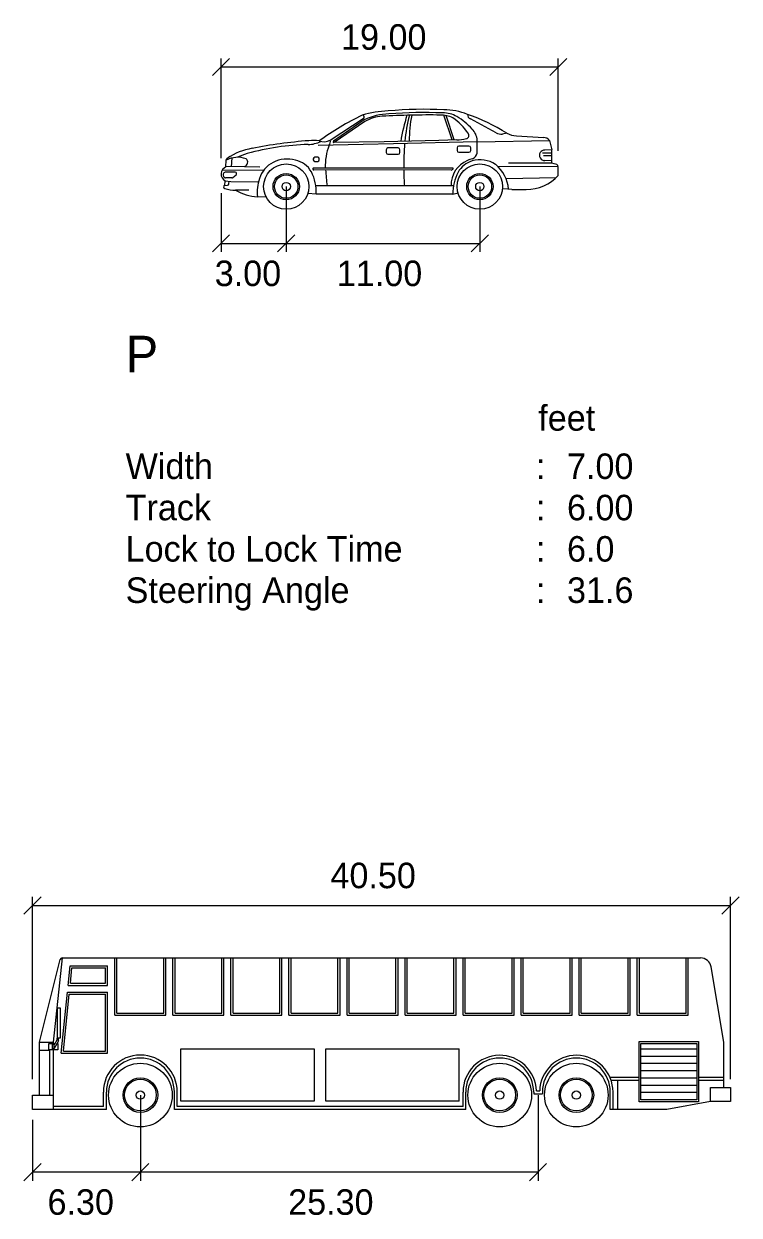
# Model space of a CAD drawing. Extents: x 2297881 to 2300600, y 559917 to 564426.
# Drawn here: x 2299070.1 to 2299106.9, y 562689.6 to 562750.9 of the extents above; entities that cross this region are included whole.
import ezdxf

# ---------------------------------------------------------------- set-up
doc = ezdxf.new("R2010")
doc.units = 0
doc.layers.add('DR_X_Elev_Flow', color=7, linetype='Continuous')

msp = doc.modelspace()

# ---------------------------------------------------------------- linework, layer by layer
at = {"layer": 'DR_X_Elev_Flow'}
for p, q in [((2299080.691, 562749.141), (2299079.805, 562748.255)), ((2299080.248, 562744.013), (2299080.248, 562749.141)), ((2299080.248, 562748.698), (2299097.593, 562748.698)), ((2299098.036, 562749.141), (2299097.15, 562748.255)), ((2299097.593, 562744.38), (2299097.593, 562749.141)), ((2299092.139, 562744.947), (2299091.71, 562746.216)), ((2299085.861, 562744.935), (2299087.611, 562746.084)), ((2299087.603, 562745.985), (2299086.034, 562744.873)), ((2299087.651, 562745.896), (2299086.071, 562744.807)), ((2299092.243, 562744.951), (2299091.824, 562746.199)), ((2299094.394, 562745.31), (2299093.077, 562746.026)), ((2299094.94, 562745.29), (2299094.721, 562745.249)), ((2299095.438, 562745.154), (2299096.83, 562745.065)), ((2299087.552, 562744.71), (2299085.242, 562744.655)), ((2299088.643, 562744.847), (2299086.055, 562744.806)), ((2299089.124, 562744.751), (2299087.552, 562744.71)), ((2299091.451, 562744.921), (2299088.643, 562744.847)), ((2299088.742, 562744.438), (2299088.742, 562744.302)), ((2299089.353, 562744.53), (2299088.834, 562744.53)), ((2299093.423, 562744.843), (2299089.124, 562744.751)), ((2299089.445, 562744.302), (2299089.445, 562744.438)), ((2299092.372, 562744.955), (2299091.451, 562744.921)), ((2299092.386, 562744.54), (2299092.386, 562744.404)), ((2299092.997, 562744.632), (2299092.478, 562744.632)), ((2299093.089, 562744.404), (2299093.089, 562744.54)), ((2299093.416, 562744.703), (2299093.423, 562744.921)), ((2299093.416, 562744.264), (2299093.416, 562744.703)), ((2299093.423, 562744.843), (2299097.144, 562744.924)), ((2299097.259, 562744.438), (2299096.899, 562744.425)), ((2299097.144, 562744.924), (2299097.259, 562744.438)), ((2299097.262, 562743.864), (2299097.259, 562744.438)), ((2299080.499, 562743.556), (2299080.513, 562743.905)), ((2299080.513, 562743.905), (2299080.577, 562744.006)), ((2299080.792, 562743.562), (2299080.817, 562744.017)), ((2299081.599, 562744.248), (2299081.091, 562744.05)), ((2299084.993, 562743.98), (2299084.993, 562743.916)), ((2299085.226, 562744.054), (2299085.067, 562744.054)), ((2299085.067, 562743.843), (2299085.226, 562743.843)), ((2299085.3, 562743.916), (2299085.3, 562743.98)), ((2299088.834, 562744.21), (2299089.353, 562744.21)), ((2299092.478, 562744.312), (2299092.997, 562744.312)), ((2299097.259, 562743.745), (2299095.032, 562743.755)), ((2299097.26, 562744.27), (2299096.786, 562744.267)), ((2299097.261, 562744.128), (2299096.826, 562744.132)), ((2299097.262, 562743.864), (2299096.895, 562743.881)), ((2299097.259, 562743.745), (2299097.262, 562743.864)), ((2299082.435, 562743.376), (2299080.306, 562743.396)), ((2299080.98, 562743.279), (2299080.454, 562743.279)), ((2299081.449, 562743.577), (2299080.499, 562743.556)), ((2299080.858, 562743.01), (2299081.027, 562743.148)), ((2299081.449, 562743.577), (2299082.249, 562743.556)), ((2299092.192, 562743.493), (2299084.983, 562743.496)), ((2299092.076, 562743.391), (2299085.018, 562743.4)), ((2299097.593, 562743.56), (2299094.491, 562743.574)), ((2299097.383, 562743.712), (2299097.259, 562743.745)), ((2299097.593, 562743.12), (2299097.593, 562743.56)), ((2299080.444, 562742.604), (2299080.462, 562742.846)), ((2299080.444, 562742.604), (2299080.588, 562742.618)), ((2299080.462, 562742.846), (2299080.752, 562742.803)), ((2299080.811, 562742.993), (2299080.469, 562742.993)), ((2299080.654, 562742.689), (2299080.658, 562742.817)), ((2299080.752, 562742.803), (2299082.138, 562742.796)), ((2299083.6, 562742.545), (2299083.6, 562739.183)), ((2299089.438, 562742.58), (2299085.123, 562742.589)), ((2299092.202, 562742.58), (2299089.438, 562742.58)), ((2299093.557, 562742.545), (2299093.557, 562739.183)), ((2299097.48, 562743.003), (2299094.91, 562742.938)), ((2299080.248, 562742.211), (2299080.248, 562739.183)), ((2299081.68, 562742.361), (2299080.987, 562742.354)), ((2299082.125, 562742.013), (2299082.548, 562742.043)), ((2299085.138, 562742.152), (2299084.709, 562742.186)), ((2299092.177, 562742.156), (2299085.138, 562742.152)), ((2299092.177, 562742.156), (2299092.437, 562742.229)), ((2299094.992, 562742.42), (2299094.718, 562742.423)), ((2299095.199, 562742.399), (2299094.992, 562742.42)), ((2299095.199, 562742.399), (2299095.939, 562742.399)), ((2299080.691, 562740.069), (2299079.805, 562739.183)), ((2299080.248, 562739.626), (2299093.557, 562739.626)), ((2299084.043, 562740.069), (2299083.157, 562739.183)), ((2299094, 562740.069), (2299093.114, 562739.183)), ((2299070.991, 562706.019), (2299070.105, 562705.133)), ((2299070.548, 562696.635), (2299070.548, 562706.019)), ((2299106.895, 562706.019), (2299106.009, 562705.133)), ((2299106.452, 562696.635), (2299106.452, 562706.019)), ((2299070.548, 562705.576), (2299106.452, 562705.576)), ((2299070.917, 562698.544), (2299071.967, 562702.792)), ((2299072.072, 562702.875), (2299071.615, 562698.538)), ((2299072.073, 562702.875), (2299104.911, 562702.875)), ((2299074.787, 562699.93), (2299074.787, 562702.875)), ((2299074.896, 562700.04), (2299074.896, 562702.875)), ((2299077.303, 562700.04), (2299077.303, 562702.875)), ((2299077.412, 562699.93), (2299077.412, 562702.875)), ((2299077.772, 562699.93), (2299077.772, 562702.875)), ((2299077.881, 562700.04), (2299077.881, 562702.875)), ((2299080.288, 562700.04), (2299080.288, 562702.875)), ((2299080.397, 562699.93), (2299080.397, 562702.875)), ((2299080.757, 562699.93), (2299080.757, 562702.875)), ((2299080.866, 562700.04), (2299080.866, 562702.875)), ((2299083.273, 562700.04), (2299083.273, 562702.875)), ((2299083.382, 562699.93), (2299083.382, 562702.875)), ((2299083.742, 562699.93), (2299083.742, 562702.875)), ((2299083.851, 562700.04), (2299083.851, 562702.875)), ((2299086.258, 562700.04), (2299086.258, 562702.875)), ((2299086.367, 562699.93), (2299086.367, 562702.875)), ((2299086.727, 562699.93), (2299086.727, 562702.875)), ((2299086.837, 562700.04), (2299086.837, 562702.875)), ((2299089.243, 562700.04), (2299089.243, 562702.875)), ((2299089.352, 562699.93), (2299089.352, 562702.875)), ((2299089.712, 562699.93), (2299089.712, 562702.875)), ((2299089.822, 562700.04), (2299089.822, 562702.875)), ((2299092.228, 562700.04), (2299092.228, 562702.875)), ((2299092.337, 562699.93), (2299092.337, 562702.875)), ((2299092.697, 562699.93), (2299092.697, 562702.875)), ((2299092.807, 562700.04), (2299092.807, 562702.875)), ((2299095.213, 562700.04), (2299095.213, 562702.875)), ((2299095.322, 562699.93), (2299095.322, 562702.875)), ((2299095.682, 562699.93), (2299095.682, 562702.875)), ((2299095.792, 562700.04), (2299095.792, 562702.875)), ((2299098.198, 562700.04), (2299098.198, 562702.875)), ((2299098.307, 562699.93), (2299098.307, 562702.875)), ((2299098.667, 562699.93), (2299098.667, 562702.875)), ((2299098.777, 562700.04), (2299098.777, 562702.875)), ((2299101.183, 562700.04), (2299101.183, 562702.875)), ((2299101.293, 562699.93), (2299101.293, 562702.875)), ((2299101.653, 562699.93), (2299101.653, 562702.875)), ((2299101.762, 562700.04), (2299101.762, 562702.875)), ((2299104.168, 562700.04), (2299104.168, 562702.875)), ((2299104.278, 562699.93), (2299104.278, 562702.875)), ((2299072.381, 562701.463), (2299072.483, 562702.477)), ((2299072.483, 562702.477), (2299074.407, 562702.477)), ((2299072.502, 562701.573), (2299072.582, 562702.367)), ((2299072.582, 562702.367), (2299074.298, 562702.367)), ((2299074.298, 562701.573), (2299074.298, 562702.367)), ((2299074.407, 562701.463), (2299074.407, 562702.477)), ((2299106.113, 562698.544), (2299105.45, 562702.42)), ((2299072.502, 562701.573), (2299074.298, 562701.573)), ((2299072.03, 562697.971), (2299072.346, 562701.118)), ((2299072.15, 562698.08), (2299072.445, 562701.008)), ((2299072.346, 562701.118), (2299074.407, 562701.118)), ((2299072.381, 562701.463), (2299074.407, 562701.463)), ((2299072.445, 562701.008), (2299074.298, 562701.008)), ((2299074.298, 562698.08), (2299074.298, 562701.008)), ((2299074.407, 562697.971), (2299074.407, 562701.118)), ((2299071.819, 562700.304), (2299071.819, 562698.741)), ((2299071.819, 562700.304), (2299071.977, 562700.304)), ((2299071.977, 562700.304), (2299071.977, 562698.741)), ((2299074.787, 562699.93), (2299077.412, 562699.93)), ((2299074.896, 562700.04), (2299077.303, 562700.04)), ((2299077.772, 562699.93), (2299080.397, 562699.93)), ((2299077.881, 562700.04), (2299080.288, 562700.04)), ((2299080.757, 562699.93), (2299083.382, 562699.93)), ((2299080.866, 562700.04), (2299083.273, 562700.04)), ((2299083.742, 562699.93), (2299086.367, 562699.93)), ((2299083.851, 562700.04), (2299086.258, 562700.04)), ((2299086.727, 562699.93), (2299089.352, 562699.93)), ((2299086.837, 562700.04), (2299089.243, 562700.04)), ((2299089.712, 562699.93), (2299092.337, 562699.93)), ((2299089.822, 562700.04), (2299092.228, 562700.04)), ((2299092.697, 562699.93), (2299095.322, 562699.93)), ((2299092.807, 562700.04), (2299095.213, 562700.04)), ((2299095.682, 562699.93), (2299098.307, 562699.93)), ((2299095.792, 562700.04), (2299098.198, 562700.04)), ((2299098.667, 562699.93), (2299101.293, 562699.93)), ((2299098.777, 562700.04), (2299101.183, 562700.04)), ((2299101.653, 562699.93), (2299104.278, 562699.93)), ((2299101.762, 562700.04), (2299104.168, 562700.04)), ((2299070.917, 562695.815), (2299070.917, 562698.544)), ((2299070.917, 562698.544), (2299071.616, 562698.544)), ((2299071.395, 562698.48), (2299071.709, 562698.48)), ((2299071.395, 562698.156), (2299071.395, 562698.48)), ((2299071.583, 562698.205), (2299071.583, 562698.432)), ((2299071.671, 562698.432), (2299071.583, 562698.432)), ((2299071.615, 562698.538), (2299071.615, 562698.48)), ((2299071.819, 562698.68), (2299071.671, 562698.41)), ((2299071.889, 562698.619), (2299071.671, 562698.222)), ((2299071.671, 562698.205), (2299071.671, 562698.432)), ((2299071.813, 562698.48), (2299071.859, 562698.48)), ((2299071.977, 562698.741), (2299071.819, 562698.741)), ((2299071.819, 562698.68), (2299071.819, 562698.741)), ((2299071.859, 562698.48), (2299071.859, 562698.156)), ((2299071.889, 562698.619), (2299071.889, 562698.741)), ((2299101.748, 562695.483), (2299101.748, 562698.575)), ((2299101.748, 562698.575), (2299104.803, 562698.575)), ((2299101.841, 562695.576), (2299101.841, 562698.482)), ((2299101.841, 562698.482), (2299104.71, 562698.482)), ((2299104.71, 562698.482), (2299104.71, 562695.576)), ((2299104.803, 562698.575), (2299104.803, 562695.483)), ((2299106.113, 562696.218), (2299106.113, 562698.544)), ((2299071.441, 562698.117), (2299070.917, 562698.117)), ((2299071.859, 562698.156), (2299071.395, 562698.156)), ((2299071.441, 562695.815), (2299071.441, 562698.117)), ((2299071.671, 562698.205), (2299071.583, 562698.205)), ((2299071.615, 562698.156), (2299071.615, 562695.088)), ((2299072.03, 562697.971), (2299074.407, 562697.971)), ((2299072.15, 562698.08), (2299074.298, 562698.08)), ((2299078.181, 562698.207), (2299085.04, 562698.207)), ((2299078.181, 562695.503), (2299078.181, 562698.207)), ((2299085.04, 562698.207), (2299085.04, 562695.503)), ((2299085.639, 562695.503), (2299085.639, 562698.207)), ((2299085.639, 562698.207), (2299092.498, 562698.207)), ((2299092.498, 562695.503), (2299092.498, 562698.207)), ((2299104.71, 562698.184), (2299101.841, 562698.184)), ((2299104.71, 562697.811), (2299101.841, 562697.811)), ((2299104.71, 562697.439), (2299101.841, 562697.439)), ((2299101.748, 562696.721), (2299100.256, 562696.721)), ((2299104.71, 562697.066), (2299101.841, 562697.066)), ((2299104.71, 562696.694), (2299101.841, 562696.694)), ((2299106.113, 562696.721), (2299104.803, 562696.721)), ((2299074.199, 562695.243), (2299074.199, 562695.98)), ((2299074.353, 562695.088), (2299074.353, 562695.98)), ((2299077.846, 562695.088), (2299077.846, 562695.98)), ((2299077.999, 562695.241), (2299077.999, 562695.98)), ((2299092.693, 562695.241), (2299092.693, 562695.98)), ((2299092.832, 562695.088), (2299092.832, 562695.98)), ((2299096.326, 562695.98), (2299096.326, 562695.882)), ((2299096.465, 562696.035), (2299096.636, 562696.035)), ((2299096.774, 562695.98), (2299096.774, 562695.882)), ((2299100.268, 562695.088), (2299100.268, 562695.98)), ((2299101.748, 562696.571), (2299100.313, 562696.571)), ((2299100.408, 562695.088), (2299100.408, 562695.98)), ((2299100.632, 562696.571), (2299100.632, 562695.088)), ((2299104.71, 562696.321), (2299101.841, 562696.321)), ((2299106.113, 562696.571), (2299104.803, 562696.571)), ((2299105.415, 562695.489), (2299105.415, 562696.218)), ((2299105.415, 562696.218), (2299106.452, 562696.218)), ((2299106.452, 562696.218), (2299106.452, 562695.489)), ((2299070.548, 562695.088), (2299070.548, 562695.815)), ((2299070.548, 562695.815), (2299071.615, 562695.815)), ((2299076.099, 562695.822), (2299076.099, 562691.42)), ((2299085.04, 562695.503), (2299078.181, 562695.503)), ((2299092.498, 562695.503), (2299085.639, 562695.503)), ((2299096.326, 562695.882), (2299096.774, 562695.882)), ((2299096.55, 562695.822), (2299096.55, 562691.42)), ((2299104.803, 562695.483), (2299101.748, 562695.483)), ((2299104.71, 562695.948), (2299101.841, 562695.948)), ((2299104.71, 562695.576), (2299101.841, 562695.576)), ((2299105.415, 562695.489), (2299103.183, 562695.088)), ((2299106.452, 562695.489), (2299105.415, 562695.489)), ((2299074.353, 562695.088), (2299070.548, 562695.088)), ((2299074.199, 562695.243), (2299071.615, 562695.243)), ((2299092.832, 562695.088), (2299077.846, 562695.088)), ((2299092.693, 562695.241), (2299077.999, 562695.241)), ((2299103.183, 562695.088), (2299100.268, 562695.088)), ((2299070.548, 562694.541), (2299070.548, 562691.42)), ((2299070.991, 562692.306), (2299070.105, 562691.42)), ((2299076.542, 562692.306), (2299075.656, 562691.42)), ((2299096.993, 562692.306), (2299096.107, 562691.42)), ((2299096.55, 562691.863), (2299070.548, 562691.863))]:
    msp.add_line(p, q, dxfattribs=at)
for centre, radius in [((2299083.6, 562742.545), 1.166), ((2299083.6, 562742.545), 0.677), ((2299083.6, 562742.545), 0.603), ((2299093.559, 562742.545), 1.166), ((2299093.559, 562742.545), 0.677), ((2299093.559, 562742.545), 0.603), ((2299083.598, 562742.545), 0.214), ((2299093.557, 562742.545), 0.214), ((2299076.099, 562695.822), 1.636), ((2299094.579, 562695.822), 1.636), ((2299098.521, 562695.822), 1.636), ((2299076.099, 562695.822), 0.891), ((2299076.099, 562695.822), 0.817), ((2299094.579, 562695.822), 0.891), ((2299094.579, 562695.822), 0.817), ((2299098.521, 562695.822), 0.891), ((2299098.521, 562695.822), 0.817), ((2299076.099, 562695.822), 0.214), ((2299094.579, 562695.822), 0.214), ((2299098.521, 562695.822), 0.214)]:
    msp.add_circle(centre, radius, dxfattribs=at)
for centre, radius, start, end in [((2299094.08, 562732.739), 14.995, 115.99712, 125.85948), ((2299089.005, 562741.248), 5.189, 91.77281, 106.76702), ((2299087.52, 562746.12), 0.098, 338.75119, 97.13803), ((2299089.008, 562742.873), 3.414, 92.05595, 114.28451), ((2299090.943, 562701.183), 45.045, 89.25909, 93.07428), ((2299090.734, 562725.354), 21.165, 87.35134, 95.12359), ((2299090.664, 562723.298), 23.056, 87.55301, 94.42581), ((2299099.097, 562743.294), 9.735, 162.55273, 170.6899), ((2299097.845, 562744.121), 8.179, 165.15925, 174.7143), ((2299096.14, 562744.957), 6.214, 168.28823, 180.7049), ((2299091.565, 562744.89), 1.334, 63.15401, 91.67876), ((2299091.665, 562744.857), 1.476, 61.06729, 90.63003), ((2299091.693, 562743.222), 3.275, 67.99072, 89.6559), ((2299093.181, 562746.266), 0.261, 181.61853, 246.57824), ((2299089.892, 562737.35), 9.408, 57.55295, 71.22582), ((2299088.676, 562744.096), 2.072, 94.12051, 119.6618), ((2299090.402, 562743.544), 3.091, 34.39064, 55.15895), ((2299090.545, 562743.155), 3.51, 41.92691, 58.50685), ((2299092.454, 562746.453), 1.5, 266.85027, 285.8201), ((2299092.823, 562745.176), 0.171, 283.52227, 41.26655), ((2299092.547, 562744.87), 0.877, 3.34282, 45.98534), ((2299094.67, 562745.881), 0.634, 244.14508, 274.63214), ((2299095.475, 562746.267), 1.114, 241.28844, 268.0918), ((2299096.837, 562744.661), 0.404, 40.57088, 90.99801), ((2299082.432, 562741.21), 3.355, 100.12542, 123.55743), ((2299085.109, 562731.36), 13.358, 91.63395, 105.23518), ((2299086.897, 562717.997), 26.993, 94.54819, 100.79455), ((2299084.721, 562746.142), 1.43, 270.28832, 297.12219), ((2299084.989, 562743.356), 1.567, 78.67608, 98.51403), ((2299085.53, 562745.552), 0.7, 250.49814, 298.18144), ((2299088.397, 562743.624), 2.79, 158.00531, 182.63231), ((2299085.566, 562744.853), 0.306, 323.15387, 15.54768), ((2299086.055, 562744.843), 0.0368, 125.3064, 270.88891), ((2299088.834, 562744.438), 0.0921, 90, 180), ((2299089.353, 562744.438), 0.0921, 0, 90), ((2299103.752, 562743.595), 14.111, 175.25332, 180.41419), ((2299092.478, 562744.54), 0.0921, 90, 180), ((2299092.478, 562744.404), 0.0921, 180, 270), ((2299092.997, 562744.54), 0.0921, 0, 90), ((2299092.997, 562744.404), 0.0921, 270, 0), ((2299096.896, 562744.153), 0.272, 89.43028, 269.87467), ((2299081.106, 562742.763), 1.288, 70.57617, 117.43529), ((2299081.392, 562743.799), 0.229, 284.46814, 51.32362), ((2299083.544, 562742.556), 1.38, 116.40845, 163.0738), ((2299083.647, 562742.335), 1.623, 74.93457, 116.18682), ((2299083.84, 562742.725), 1.2, 28.74798, 78.99952), ((2299085.067, 562743.98), 0.0736, 90, 180), ((2299085.067, 562743.916), 0.0736, 180, 270), ((2299085.226, 562743.98), 0.0736, 0, 90), ((2299085.226, 562743.916), 0.0736, 270, 360), ((2299088.834, 562744.302), 0.0921, 180, 270), ((2299089.353, 562744.302), 0.0921, 270, 0), ((2299093.434, 562742.626), 1.357, 112.09642, 181.96798), ((2299093.548, 562742.637), 1.288, 107.40375, 149.71305), ((2299093.337, 562743.12), 0.869, 100.40941, 118.442), ((2299093.562, 562742.398), 1.521, 58.12537, 105.22231), ((2299093.035, 562744.333), 0.387, 292.0027, 349.73442), ((2299080.637, 562743.193), 0.388, 110.80508, 243.2128), ((2299080.532, 562743.144), 0.173, 142.05963, 230.7171), ((2299080.454, 562743.205), 0.0736, 90, 142.05963), ((2299080.98, 562743.205), 0.0736, 309.39036, 90), ((2299082.996, 562742.294), 2.147, 356.20605, 28.00521), ((2299085.023, 562743.456), 0.0565, 134.52898, 265.08732), ((2299112.364, 562745.398), 26.813, 184.27566, 186.01704), ((2299096.256, 562743.207), 6.604, 178.40363, 185.45034), ((2299092.075, 562743.509), 0.118, 270.588, 352.21402), ((2299094.435, 562742.235), 2.26, 152.25545, 181.99873), ((2299093.11, 562742.209), 1.941, 6.08396, 49.72235), ((2299097.399, 562743.513), 0.2, 13.74091, 94.60676), ((2299080.455, 562742.529), 0.0757, 98.08536, 261.91464), ((2299080.469, 562743.067), 0.0736, 230.7171, 270), ((2299080.58, 562742.692), 0.0736, 275.90147, 358.12063), ((2299080.811, 562743.067), 0.0736, 270, 309.39036), ((2299084.159, 562742.277), 2.051, 160.61524, 187.39409), ((2299095.975, 562744.575), 2.176, 269.05415, 318.03413), ((2299081.004, 562743.969), 1.615, 249.72886, 269.41245), ((2299082.35, 562744.835), 2.831, 241.23216, 265.44658), ((2299072.073, 562702.765), 0.109, 90, 166.11417), ((2299104.911, 562702.328), 0.547, 9.69899, 90), ((2299076.099, 562695.98), 1.9, 0, 180), ((2299094.579, 562695.98), 1.887, 1.66761, 180), ((2299098.521, 562695.98), 1.887, 0, 178.33239), ((2299076.099, 562695.98), 1.747, 0, 180), ((2299094.579, 562695.98), 1.747, 0, 180), ((2299098.521, 562695.98), 1.747, 0, 180)]:
    msp.add_arc(centre, radius, start, end, dxfattribs=at)

# ---------------------------------------------------------------- texts
for s, height, p in [('19.00', 1.3123, (2299086.421, 562749.584)), ('3.00', 1.3123, (2299079.924, 562737.427)), ('11.00', 1.3123, (2299086.204, 562737.427)), ('P', 1.875, (2299075.342, 562732.998)), ('feet', 1.3123, (2299096.563, 562729.991)), ('Width', 1.3123, (2299075.342, 562727.507)), (':', 1.312, (2299096.446, 562727.507)), ('7.00', 1.3123, (2299098.041, 562727.507)), ('Track', 1.3123, (2299075.342, 562725.382)), ('6.00', 1.3123, (2299098.041, 562725.382)), (':', 1.312, (2299096.446, 562725.382)), ('Lock to Lock Time', 1.31234, (2299075.342, 562723.258)), (':', 1.312, (2299096.446, 562723.258)), ('6.0', 1.3123, (2299098.041, 562723.258)), ('Steering Angle', 1.31234, (2299075.342, 562721.133)), ('31.6', 1.3123, (2299098.041, 562721.133)), (':', 1.312, (2299096.446, 562721.133)), ('40.50', 1.3123, (2299085.875, 562706.462)), ('6.30', 1.3123, (2299071.324, 562689.665)), ('25.30', 1.3123, (2299083.7, 562689.665))]:
    msp.add_text(s, height=height, dxfattribs=at).set_placement(p)

doc.saveas('drawing.dxf')
